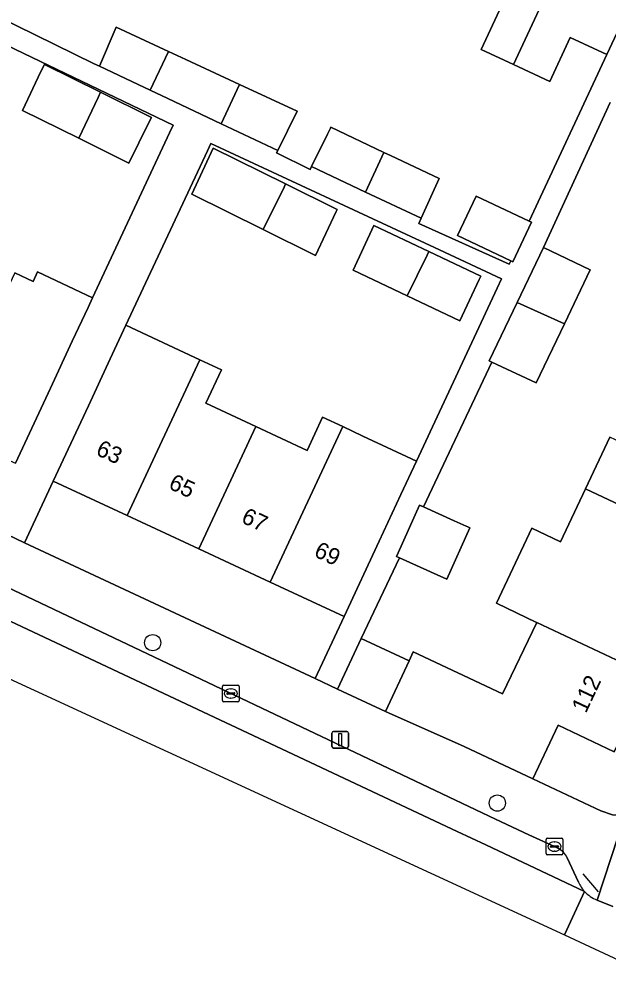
# Model space of a CAD drawing. Extents: x 159817 to 160765, y 380688 to 381638.
# Drawn here: x 160000.7 to 160036.2, y 381177.7 to 381234.9 of the extents above; entities that cross this region are included whole.
import ezdxf

# ---------------------------------------------------------------- set-up
doc = ezdxf.new("R2010")
doc.units = 0
for name, color, linetype in [('IMGEO_Boom', 7, 'Continuous'), ('IMGEO_Erf', 7, 'Continuous'), ('IMGEO_Hek', 7, 'Continuous'), ('IMGEO_Kolk', 7, 'Continuous'), ('IMGEO_Lichtmast', 7, 'Continuous'), ('IMGEO_Muur', 7, 'Continuous'), ('IMGEO_Pand', 7, 'Continuous'), ('IMGEO_Pand_nummerreeks', 7, 'Continuous'), ('IMGEO_Parkeervlak_open', 7, 'Continuous'), ('IMGEO_Rijbaan_lokaal_open', 7, 'Continuous'), ('IMGEO_Voetpad_open', 7, 'Continuous')]:
    doc.layers.add(name, color=color, linetype=linetype)

msp = doc.modelspace()

# ---------------------------------------------------------------- linework, layer by layer
at = {"layer": 'IMGEO_Boom'}
for centre in [(160008.776, 381197.276), (160029.555, 381187.602)]:
    msp.add_circle(centre, 0.489, dxfattribs=at)
at = {"layer": 'IMGEO_Erf'}
for points in [[(159998.145, 381235.668), (160005.246, 381232.194), (160005.573, 381232.045), (160006.582, 381234.391), (160009.721, 381232.935), (160010.782, 381232.443), (160014.014, 381230.944), (160017.478, 381229.336), (160016.317, 381226.962), (160016.244, 381226.813), (160018.273, 381225.821), (160018.358, 381225.996), (160019.315, 381227.946), (160019.491, 381228.304), (160019.517, 381228.358), (160022.721, 381226.842), (160023.109, 381226.666), (160026.052, 381225.274), (160024.964, 381222.87), (160024.825, 381222.563), (160030.267, 381220.1), (160030.367, 381220.314), (160027.162, 381221.83), (160028.29, 381224.215), (160031.482, 381222.705), (160036.165, 381232.742), (160033.953, 381233.774), (160032.716, 381231.121), (160030.531, 381232.14), (160028.575, 381233.052), (160029.827, 381235.735)], [(160057.89, 381233.73), (160053.601, 381235.7), (160052.088, 381232.486), (160055.443, 381230.907), (160053.272, 381226.294), (160051.101, 381221.683), (160047.771, 381223.25), (160046.276, 381220.074), (160044.781, 381216.898), (160048.175, 381215.3), (160046.025, 381210.732), (160043.874, 381206.163), (160040.489, 381207.757), (160039.007, 381204.608), (160037.525, 381201.46), (160040.922, 381199.861), (160038.765, 381195.278), (160036.608, 381190.697), (160033.22, 381192.292), (160031.696, 381189.056), (160035.794, 381187.126), (160036.497, 381186.883), (160037.238, 381186.827)], [(160000.46, 381219.588), (160001.567, 381219.065), (160001.835, 381219.64), (160005.148, 381218.075), (160009.785, 381228.03), (160010, 381228.493), (159996.961, 381234.733)], [(160036.361, 381229.849), (160032.331, 381221.109), (160035.156, 381219.759), (160033.597, 381216.496), (160031.898, 381212.942), (160029.221, 381214.195), (160025.097, 381205.463), (160026.95, 381204.632), (160027.682, 381204.304), (160027.773, 381204.263), (160027.894, 381204.209), (160026.503, 381201.111), (160025.92, 381201.373), (160023.647, 381202.393), (160021.352, 381197.534), (160024.242, 381196.188), (160024.488, 381196.716), (160029.862, 381194.184), (160031.936, 381198.489), (160031.925, 381198.494), (160029.507, 381199.661), (160031.639, 381204.191), (160033.367, 381203.365), (160034.87, 381206.557), (160036.337, 381209.674)]]:
    msp.add_lwpolyline(points, dxfattribs=at)
for points in [[(160000.922, 381229.382), (160002.036, 381231.717), (160002.242, 381232.148), (160005.626, 381230.472), (160008.702, 381228.949), (160008.55, 381228.642), (160007.341, 381226.203), (160004.312, 381227.703)], [(160029.545, 381218.657), (160029.805, 381219.215), (160025.759, 381221.103), (160012.279, 381227.391), (160012.072, 381226.948), (160007.16, 381216.419), (160010.361, 381214.926), (160011.611, 381214.343), (160012.915, 381213.736), (160011.977, 381211.724), (160014.989, 381210.321), (160018.094, 381208.874), (160019.024, 381210.87), (160020.235, 381210.306), (160021.451, 381209.739), (160024.684, 381208.232)], [(160016.79, 381224.942), (160019.897, 381223.403), (160019.836, 381223.274), (160018.586, 381220.632), (160015.444, 381222.189), (160011.131, 381224.325), (160012.303, 381226.838), (160012.427, 381227.103)], [(160025.434, 381220.867), (160028.56, 381219.387), (160028.458, 381219.171), (160027.287, 381216.696), (160024.119, 381218.195), (160020.86, 381219.736), (160022.119, 381222.435)], [(160011.548, 381202.941), (160007.232, 381204.952), (160002.782, 381207.026), (160001.047, 381203.302), (160018.569, 381195.113), (160020.314, 381198.856), (160015.863, 381200.93)]]:
    msp.add_lwpolyline(points, close=True, dxfattribs=at)
at = {"layer": 'IMGEO_Hek'}
msp.add_lwpolyline([(160034.703, 381183.332), (160035.632, 381182.258)], dxfattribs=at)
at = {"layer": 'IMGEO_Kolk'}
for p, q in [((160012.984, 381193.785), (160012.984, 381194.637)), ((160013.059, 381194.711), (160013.911, 381194.711)), ((160013.472, 381194.491), (160013.497, 381194.491)), ((160013.985, 381194.637), (160013.985, 381193.785)), ((160013.911, 381193.711), (160013.059, 381193.711)), ((160013.243, 381194.205), (160013.243, 381194.217)), ((160013.681, 381194.168), (160013.283, 381194.168)), ((160013.286, 381194.254), (160013.684, 381194.254)), ((160013.495, 381193.931), (160013.47, 381193.931)), ((160013.727, 381194.217), (160013.727, 381194.205)), ((160032.503, 381184.552), (160032.503, 381185.404)), ((160032.578, 381185.478), (160033.43, 381185.478)), ((160032.991, 381185.258), (160033.016, 381185.258)), ((160033.504, 381185.404), (160033.504, 381184.552)), ((160032.762, 381184.972), (160032.762, 381184.984)), ((160033.2, 381184.935), (160032.802, 381184.935)), ((160032.805, 381185.021), (160033.203, 381185.021)), ((160033.014, 381184.698), (160032.989, 381184.698)), ((160033.246, 381184.984), (160033.246, 381184.972)), ((160033.43, 381184.478), (160032.578, 381184.478))]:
    msp.add_line(p, q, dxfattribs=at)
for points in [[(160012.984, 381193.785), (160012.984, 381194.637)], [(160013.059, 381194.711), (160013.911, 381194.711)], [(160013.985, 381194.637), (160013.985, 381193.785)], [(160013.911, 381193.711), (160013.059, 381193.711)], [(160032.503, 381184.552), (160032.503, 381185.404)], [(160032.578, 381185.478), (160033.43, 381185.478)], [(160033.504, 381185.404), (160033.504, 381184.552)], [(160033.43, 381184.478), (160032.578, 381184.478)]]:
    msp.add_lwpolyline(points, dxfattribs=at)
for centre, radius, start, end in [((160013.061, 381194.635), 0.0765, 91.552, 178.448), ((160013.061, 381194.635), 0.0765, 91.552, 178.448), ((160013.909, 381194.635), 0.0765, 1.552, 88.448), ((160013.909, 381194.635), 0.0765, 1.552, 88.448), ((160013.061, 381193.787), 0.0765, 181.552, 268.448), ((160013.061, 381193.787), 0.0765, 181.552, 268.448), ((160013.283, 381194.214), 0.0403, 85.8775, 175.7526), ((160013.28, 381194.204), 0.0366, 178.938, 274.7102), ((160013.684, 381194.211), 0.043, 264.8664, 352.4533), ((160013.688, 381194.216), 0.0386, 1.7309, 96.639), ((160013.909, 381193.787), 0.0765, 271.552, 358.448), ((160013.909, 381193.787), 0.0765, 271.552, 358.448), ((160032.58, 381185.402), 0.0765, 91.552, 178.448), ((160032.58, 381185.402), 0.0765, 91.552, 178.448), ((160033.428, 381185.402), 0.0765, 1.552, 88.448), ((160033.428, 381185.402), 0.0765, 1.552, 88.448), ((160032.58, 381184.554), 0.0765, 181.552, 268.448), ((160032.58, 381184.554), 0.0765, 181.552, 268.448), ((160032.802, 381184.981), 0.0403, 85.8775, 175.7526), ((160032.799, 381184.971), 0.0366, 178.938, 274.7102), ((160033.203, 381184.978), 0.043, 264.8664, 352.4533), ((160033.207, 381184.983), 0.0386, 1.7309, 96.639), ((160033.428, 381184.554), 0.0765, 271.552, 358.448), ((160033.428, 381184.554), 0.0765, 271.552, 358.448)]:
    msp.add_arc(centre, radius, start, end, dxfattribs=at)
for centre, major_axis, ratio, start_param, end_param in [((160013.471, 381194.211), (-0.387, 0.002), 0.722429, 4.712389, 7.853982), ((160013.496, 381194.211), (-0.39, 0.002), 0.717154, 1.570796, 4.712389), ((160032.99, 381184.978), (-0.387, 0.002), 0.722429, 4.712389, 7.853982), ((160033.015, 381184.978), (-0.39, 0.002), 0.717154, 1.570796, 4.712389)]:
    msp.add_ellipse(centre, major_axis=major_axis, ratio=ratio, start_param=start_param, end_param=end_param, dxfattribs=at)
at = {"layer": 'IMGEO_Lichtmast'}
for p, q in [((160019.582, 381191.022), (160019.582, 381191.822)), ((160019.582, 381191.822), (160019.582, 381191.022)), ((160019.682, 381191.922), (160020.472, 381191.922)), ((160020.472, 381191.922), (160019.682, 381191.922)), ((160020.572, 381191.822), (160020.572, 381191.022)), ((160020.572, 381191.022), (160020.572, 381191.822)), ((160020.472, 381190.922), (160019.682, 381190.922)), ((160019.682, 381190.922), (160020.472, 381190.922))]:
    msp.add_line(p, q, dxfattribs=at)
msp.add_lwpolyline([(160020.002, 381191.797), (160020.152, 381191.797), (160020.152, 381191.047), (160020.002, 381191.047), (160020.002, 381191.797)], dxfattribs=at)
for centre, start, end in [((160019.682, 381191.822), 90, 180), ((160019.682, 381191.822), 90, 180), ((160020.472, 381191.822), 0, 90), ((160020.472, 381191.822), 360, 90), ((160019.682, 381191.022), 180, 270), ((160019.682, 381191.022), 180, 270), ((160020.472, 381191.022), 270, 0), ((160020.472, 381191.022), 270, 0)]:
    msp.add_arc(centre, 0.1, start, end, dxfattribs=at)
at = {"layer": 'IMGEO_Muur'}
msp.add_lwpolyline([(160022.818, 381193.132), (160027.551, 381191.007)], dxfattribs=at)
at = {"layer": 'IMGEO_Pand'}
for points in [[(160030.531, 381232.14), (160036.021, 381243.93), (160033.032, 381245.322), (160031.617, 381245.981), (160028.491, 381239.262), (160027.382, 381236.875), (160029.827, 381235.735), (160028.575, 381233.052)], [(160030.531, 381232.14), (160032.716, 381231.121), (160033.953, 381233.774), (160036.165, 381232.742), (160038.313, 381237.347), (160040.426, 381241.878), (160036.021, 381243.93)], [(160009.721, 381232.935), (160006.582, 381234.391), (160005.573, 381232.045), (160007.908, 381230.94), (160008.629, 381230.599)], [(160014.014, 381230.944), (160010.782, 381232.443), (160009.721, 381232.935), (160008.629, 381230.599), (160009.692, 381230.096), (160012.903, 381228.577)], [(160005.479, 381230.163), (160005.626, 381230.472), (160002.242, 381232.148), (160002.036, 381231.717), (160000.922, 381229.382), (160004.312, 381227.703)], [(160017.478, 381229.336), (160014.014, 381230.944), (160012.903, 381228.577), (160016.317, 381226.962)], [(160008.55, 381228.642), (160008.702, 381228.949), (160005.626, 381230.472), (160005.479, 381230.163), (160004.312, 381227.703), (160007.341, 381226.203)], [(160022.721, 381226.842), (160019.517, 381228.358), (160019.491, 381228.304), (160019.315, 381227.946), (160018.358, 381225.996), (160021.612, 381224.456)], [(160016.7, 381224.758), (160016.79, 381224.942), (160012.427, 381227.103), (160012.303, 381226.838), (160011.131, 381224.325), (160015.444, 381222.189)], [(160026.052, 381225.274), (160023.109, 381226.666), (160022.721, 381226.842), (160021.612, 381224.456), (160024.964, 381222.87)], [(160019.836, 381223.274), (160019.897, 381223.403), (160016.79, 381224.942), (160016.7, 381224.758), (160015.444, 381222.189), (160018.586, 381220.632)], [(160031.482, 381222.705), (160028.29, 381224.215), (160027.162, 381221.83), (160030.367, 381220.314), (160030.493, 381220.254), (160031.622, 381222.639)], [(160025.328, 381220.652), (160025.434, 381220.867), (160022.119, 381222.435), (160020.86, 381219.736), (160024.119, 381218.195)], [(160028.458, 381219.171), (160028.56, 381219.387), (160025.434, 381220.867), (160025.328, 381220.652), (160024.119, 381218.195), (160027.287, 381216.696)], [(160033.597, 381216.496), (160035.156, 381219.759), (160032.331, 381221.109), (160030.748, 381217.795)], [(160003.927, 381215.454), (160004.88, 381217.5), (160005.148, 381218.075), (160001.835, 381219.64), (160001.567, 381219.065), (160000.46, 381219.588), (160000.001, 381218.606), (159996.063, 381210.173), (160000, 381208.333), (160000.5, 381208.099), (160002.612, 381212.632)], [(160033.597, 381216.496), (160030.748, 381217.795), (160029.063, 381214.269), (160029.221, 381214.195), (160031.898, 381212.942)], [(160007.232, 381204.952), (160011.611, 381214.343), (160010.361, 381214.926), (160007.16, 381216.419), (160006.213, 381214.389), (160004.894, 381211.559), (160002.782, 381207.026)], [(160011.548, 381202.941), (160014.989, 381210.321), (160011.977, 381211.724), (160012.915, 381213.736), (160011.611, 381214.343), (160007.232, 381204.952)], [(160039.189, 381213.95), (160037.024, 381209.351), (160036.337, 381209.674), (160034.87, 381206.557), (160039.007, 381204.608), (160040.489, 381207.757), (160043.874, 381206.163), (160046.025, 381210.732)], [(160011.548, 381202.941), (160015.863, 381200.93), (160020.235, 381210.306), (160019.024, 381210.87), (160018.094, 381208.874), (160014.989, 381210.321)], [(160015.863, 381200.93), (160020.314, 381198.856), (160022.427, 381203.389), (160023.738, 381206.203), (160024.684, 381208.232), (160021.451, 381209.739), (160020.235, 381210.306)], [(160037.525, 381201.46), (160039.007, 381204.608), (160034.87, 381206.557), (160033.367, 381203.365), (160031.639, 381204.191), (160029.507, 381199.661), (160031.925, 381198.494), (160031.936, 381198.489), (160038.765, 381195.278), (160040.922, 381199.861)], [(160026.95, 381204.632), (160025.097, 381205.463), (160024.859, 381205.57), (160023.571, 381202.701), (160023.468, 381202.473), (160023.647, 381202.393), (160025.92, 381201.373), (160026.503, 381201.111), (160027.894, 381204.209), (160027.773, 381204.263), (160027.682, 381204.304)], [(160038.765, 381195.278), (160031.936, 381198.489), (160029.862, 381194.184), (160024.488, 381196.716), (160024.242, 381196.188), (160022.818, 381193.132), (160027.551, 381191.007), (160031.696, 381189.056), (160033.22, 381192.292), (160036.608, 381190.697)], [(160022.818, 381193.132), (160024.242, 381196.188), (160021.352, 381197.534), (160019.928, 381194.478)]]:
    msp.add_lwpolyline(points, close=True, dxfattribs=at)
at = {"layer": 'IMGEO_Parkeervlak_open'}
for points in [[(159946.039, 381224.044), (160027.136, 381185.888), (160028.867, 381185.073), (160034.817, 381182.274)], [(160033.209, 381184.876), (160033.004, 381184.977), (160031.446, 381185.682), (160029.441, 381186.629), (160000, 381200.627), (159958.569, 381219.768)], [(160034.45, 381182.829), (160033.769, 381184.305)]]:
    msp.add_lwpolyline(points, dxfattribs=at)
for centre, radius, start, end in [((160032.67, 381183.787), 1.215, 25.2204, 63.6651), ((160036.347, 381183.685), 2.081, 204.2756, 222.6746)]:
    msp.add_arc(centre, radius, start, end, dxfattribs=at)
at = {"layer": 'IMGEO_Rijbaan_lokaal_open'}
for points in [[(159932.129, 381228.694), (159929.706, 381229.282), (159929.416, 381229.352), (159920.733, 381230.853), (159920.531, 381230.844), (159920.986, 381227.331), (159935.277, 381225.033), (159945.455, 381220.334), (160033.598, 381179.646)], [(160033.598, 381179.646), (160034.817, 381182.274), (160028.867, 381185.073), (160027.136, 381185.888), (159946.039, 381224.044), (159940.67, 381226.048), (159936.62, 381227.432)], [(160034.817, 381182.274), (160033.598, 381179.646), (160037.786, 381177.712)], [(160036.519, 381181.371), (160035.567, 381181.755)]]:
    msp.add_lwpolyline(points, dxfattribs=at)
msp.add_arc((160036.346, 381183.683), 2.079, 222.6469, 247.9867, dxfattribs=at)
at = {"layer": 'IMGEO_Voetpad_open'}
for points in [[(160027.551, 381191.007), (160022.818, 381193.132), (160019.928, 381194.478), (160018.569, 381195.113), (160001.047, 381203.302), (160000, 381203.791), (159998.756, 381204.372), (159972.688, 381216.555), (159970.395, 381217.626), (159953.122, 381225.698), (159949.541, 381227.371), (159946.01, 381228.96), (159945.955, 381228.985), (159944.822, 381230.532), (159944.819, 381230.536), (159939.817, 381237.365), (159937.076, 381241.217), (159931.92, 381248.398), (159932.15, 381249.827), (159927.383, 381246.311)], [(160038.313, 381237.347), (160036.165, 381232.742), (160031.482, 381222.705), (160031.622, 381222.639), (160030.493, 381220.254), (160030.367, 381220.314), (160030.267, 381220.1), (160024.825, 381222.563), (160024.964, 381222.87), (160021.612, 381224.456), (160018.358, 381225.996), (160018.273, 381225.821), (160016.244, 381226.813), (160016.317, 381226.962), (160012.903, 381228.577), (160009.692, 381230.096), (160008.629, 381230.599), (160007.908, 381230.94), (160005.573, 381232.045), (160005.246, 381232.194), (159998.145, 381235.668)], [(159996.961, 381234.733), (160010, 381228.493), (160009.785, 381228.03), (160005.148, 381218.075), (160004.88, 381217.5), (160003.927, 381215.454), (160002.612, 381212.632), (160000.5, 381208.099)], [(160000, 381203.791), (160001.047, 381203.302), (160002.782, 381207.026), (160004.894, 381211.559), (160006.213, 381214.389), (160007.16, 381216.419), (160012.072, 381226.948), (160012.279, 381227.391), (160025.759, 381221.103), (160029.805, 381219.215), (160029.545, 381218.657), (160024.684, 381208.232), (160023.738, 381206.203), (160022.427, 381203.389), (160020.314, 381198.856), (160018.569, 381195.113), (160019.928, 381194.478), (160021.352, 381197.534), (160023.647, 381202.393), (160023.468, 381202.473), (160023.571, 381202.701), (160024.859, 381205.57), (160025.097, 381205.463), (160029.221, 381214.195), (160029.063, 381214.269), (160030.748, 381217.795), (160032.331, 381221.109), (160036.361, 381229.849)], [(159949.126, 381224.219), (159958.569, 381219.768), (160000, 381200.627), (160029.441, 381186.629), (160031.446, 381185.682), (160033.004, 381184.977), (160033.209, 381184.876)], [(160035.567, 381181.755), (160037.238, 381186.827), (160036.497, 381186.883), (160035.794, 381187.126), (160031.696, 381189.056), (160027.551, 381191.007)], [(160037.238, 381186.827), (160035.567, 381181.755), (160036.519, 381181.371)], [(160033.769, 381184.305), (160034.45, 381182.829)]]:
    msp.add_lwpolyline(points, dxfattribs=at)
for centre, radius, start, end in [((160032.67, 381183.787), 1.215, 25.2204, 63.6651), ((160036.347, 381183.685), 2.081, 204.2756, 222.6746), ((160036.346, 381183.683), 2.079, 222.6469, 247.9867)]:
    msp.add_arc(centre, radius, start, end, dxfattribs=at)

# ---------------------------------------------------------------- texts
at = {"layer": 'IMGEO_Pand_nummerreeks'}
for s, rotation, p in [('63', 335.0142, (160005.288, 381208.637)), ('65', 335.0142, (160009.671, 381206.595)), ('67', 335.0142, (160014.054, 381204.552)), ('69', 335.0142, (160018.437, 381202.51)), ('112', 64.7901, (160034.896, 381192.976))]:
    msp.add_text(s, height=1, rotation=rotation, dxfattribs=at).set_placement(p)

doc.saveas('drawing.dxf')
